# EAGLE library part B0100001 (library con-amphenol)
AMPHENOL CONNECTOR
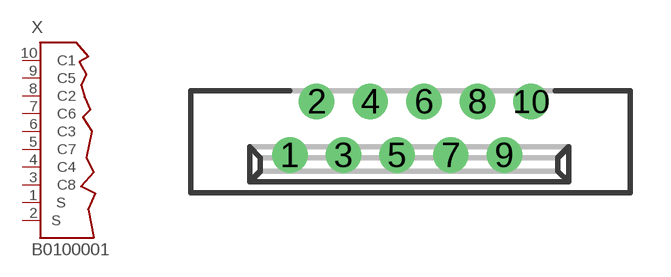
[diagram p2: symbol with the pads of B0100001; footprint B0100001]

Designator prefix X

## B0100001 (MF: AMPHENOL; MPN: C00710B0100001; OC_FARNELL: unknown; OC_NEWARK: 07C1371)  [B0100001]
1  S2  pas
2  S1  pas
3  C8  pas
4  C4  pas
5  C7  pas
6  C3  pas
7  C6  pas
8  C2  pas
9  C5  pas
10  C1  pas

## Footprint B0100001 (pad centres in mm)
AMPHENOL CONNECTOR
drill 0.813 round: 1 -4.5,-1; 2 -3.5,1; 3 -2.5,-1; 4 -1.5,1; 5 -0.5,-1; 6 0.5,1; 7 1.5,-1; 8 2.5,1; 9 3.5,-1; 10 4.5,1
